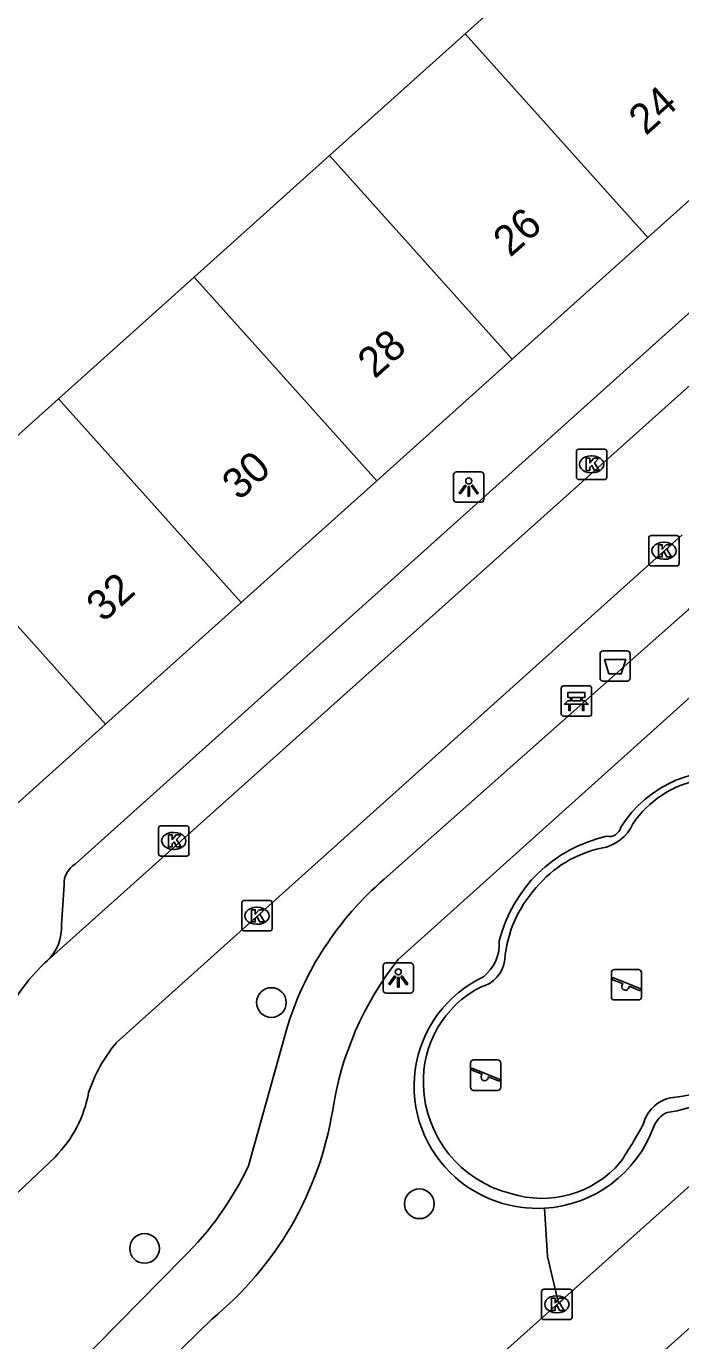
# Model space of a CAD drawing. Extents: x 162172 to 163187, y 382874 to 383684.
# Drawn here: x 162860.48 to 162882.03, y 383428.41 to 383471.71 of the extents above; entities that cross this region are included whole.
import ezdxf

# ---------------------------------------------------------------- set-up
doc = ezdxf.new("R2010")
doc.units = 0
for name, color, linetype in [('IMGEO_Afvalbak', 7, 'Continuous'), ('IMGEO_Bank', 7, 'Continuous'), ('IMGEO_Berm_groen', 7, 'Continuous'), ('IMGEO_Boom', 7, 'Continuous'), ('IMGEO_Haag', 7, 'Continuous'), ('IMGEO_Kolk', 7, 'Continuous'), ('IMGEO_Lichtpunt', 7, 'Continuous'), ('IMGEO_Pand', 7, 'Continuous'), ('IMGEO_Pand_nummerreeks', 7, 'Continuous'), ('IMGEO_Rijbaan_lokaal_open', 7, 'Continuous'), ('IMGEO_Speelvoorziening', 7, 'Continuous'), ('IMGEO_Terreindeel_open', 7, 'Continuous'), ('IMGEO_Voetpad_open', 7, 'Continuous')]:
    doc.layers.add(name, color=color, linetype=linetype)

msp = doc.modelspace()

# ---------------------------------------------------------------- linework, layer by layer
at = {"layer": 'IMGEO_Afvalbak'}
for p, q in [((162879.479, 383451.136), (162880.269, 383451.136)), ((162880.269, 383451.136), (162879.479, 383451.136)), ((162879.379, 383450.236), (162879.379, 383451.036)), ((162879.379, 383451.036), (162879.379, 383450.236)), ((162880.369, 383451.036), (162880.369, 383450.236)), ((162880.369, 383450.236), (162880.369, 383451.036)), ((162880.269, 383450.136), (162879.479, 383450.136)), ((162879.479, 383450.136), (162880.269, 383450.136))]:
    msp.add_line(p, q, dxfattribs=at)
msp.add_lwpolyline([(162879.522, 383450.85), (162880.226, 383450.85), (162880.077, 383450.38), (162879.671, 383450.38), (162879.522, 383450.85)], dxfattribs=at)
for centre, start, end in [((162879.479, 383451.036), 90, 180), ((162879.479, 383451.036), 90, 180), ((162880.269, 383451.036), 0, 90), ((162880.269, 383451.036), 360, 90), ((162879.479, 383450.236), 180, 270), ((162879.479, 383450.236), 180, 270), ((162880.269, 383450.236), 270, 0), ((162880.269, 383450.236), 270, 0)]:
    msp.add_arc(centre, 0.1, start, end, dxfattribs=at)
at = {"layer": 'IMGEO_Bank'}
for p, q in [((162878.1, 383449.06), (162878.1, 383449.901)), ((162878.1, 383449.901), (162878.1, 383449.06)), ((162878.175, 383449.985), (162879.016, 383449.985)), ((162879.016, 383449.985), (162878.175, 383449.985)), ((162879.1, 383449.91), (162879.1, 383449.069)), ((162879.1, 383449.069), (162879.1, 383449.91)), ((162878.797, 383449.383), (162878.404, 383449.383)), ((162878.409, 383449.491), (162878.409, 383449.597)), ((162878.453, 383449.597), (162878.453, 383449.491)), ((162878.741, 383449.603), (162878.459, 383449.603)), ((162878.459, 383449.485), (162878.741, 383449.485)), ((162878.747, 383449.491), (162878.747, 383449.597)), ((162878.791, 383449.597), (162878.791, 383449.491)), ((162879.025, 383448.985), (162878.184, 383448.985)), ((162878.184, 383448.985), (162879.025, 383448.985))]:
    msp.add_line(p, q, dxfattribs=at)
for points in [[(162878.403, 383449.603), (162878.317, 383449.603), (162878.317, 383449.764), (162878.88, 383449.764), (162878.88, 383449.603), (162878.797, 383449.603)], [(162878.347, 383449.383), (162878.205, 383449.383), (162878.317, 383449.485), (162878.403, 383449.485)], [(162878.397, 383449.376), (162878.397, 383449.169), (162878.354, 383449.169), (162878.354, 383449.376)], [(162878.797, 383449.485), (162878.88, 383449.485), (162878.992, 383449.383), (162878.853, 383449.383)], [(162878.847, 383449.376), (162878.847, 383449.169), (162878.803, 383449.169), (162878.803, 383449.376)]]:
    msp.add_lwpolyline(points, dxfattribs=at)
for centre, radius, start, end in [((162878.178, 383449.907), 0.0779, 92.4484, 184.2845), ((162878.178, 383449.907), 0.0779, 92.4484, 184.2845), ((162879.022, 383449.907), 0.0779, 2.4484, 94.2845), ((162879.022, 383449.907), 0.0779, 2.4484, 94.2845), ((162878.347, 383449.376), 0.00671, 2.8957, 87.1043), ((162878.404, 383449.376), 0.00671, 92.8957, 177.1043), ((162878.402, 383449.596), 0.00671, 2.8957, 87.1043), ((162878.402, 383449.492), 0.00671, 272.8957, 357.1043), ((162878.459, 383449.596), 0.00671, 92.8957, 177.1043), ((162878.459, 383449.492), 0.00671, 182.8957, 267.1043), ((162878.741, 383449.596), 0.00671, 2.8957, 87.1043), ((162878.741, 383449.492), 0.00671, 272.8957, 357.1043), ((162878.798, 383449.596), 0.00671, 92.8957, 177.1043), ((162878.798, 383449.492), 0.00671, 182.8957, 267.1043), ((162878.796, 383449.376), 0.00671, 2.8957, 87.1043), ((162878.853, 383449.376), 0.00671, 92.8957, 177.1043), ((162878.178, 383449.063), 0.0779, 182.4484, 274.2845), ((162878.178, 383449.063), 0.0779, 182.4484, 274.2845), ((162879.022, 383449.063), 0.0779, 272.4484, 4.2845), ((162879.022, 383449.063), 0.0779, 272.4484, 4.2845)]:
    msp.add_arc(centre, radius, start, end, dxfattribs=at)
at = {"layer": 'IMGEO_Berm_groen'}
for centre, radius, start, end in [((162883.45, 383443.191), 4.004, 9.0634, 147.8309), ((162880.6, 383440.457), 4.678, 102.4127, 166.06), ((162879.676, 383445.413), 0.395, 258.0117, 346.899), ((162874.663, 383441.491), 1.399, 308.7042, 3.8292), ((162877.24, 383436.792), 3.988, 115.2604, 228.8582), ((162877.313, 383436.845), 4.076, 228.5736, 273.2824)]:
    msp.add_arc(centre, radius, start, end, dxfattribs=at)
at = {"layer": 'IMGEO_Boom'}
for centre in [(162868.552, 383439.551), (162873.426, 383432.921), (162864.375, 383431.45)]:
    msp.add_circle(centre, 0.489, dxfattribs=at)
at = {"layer": 'IMGEO_Haag'}
msp.add_lwpolyline([(162877.546, 383432.776), (162877.648, 383431.184), (162878.014, 383429.65)], dxfattribs=at)
for centre, radius, start, end in [((162881.087, 383440.039), 4.137, 276.9729, 349.396), ((162881.998, 383435.107), 0.922, 116.3265, 157.1983), ((162877.312, 383436.846), 4.077, 273.2851, 340.1793)]:
    msp.add_arc(centre, radius, start, end, dxfattribs=at)
at = {"layer": 'IMGEO_Kolk'}
for p, q in [((162878.6, 383456.853), (162878.6, 383457.705)), ((162878.675, 383457.779), (162879.527, 383457.779)), ((162879.088, 383457.559), (162879.113, 383457.559)), ((162879.601, 383457.705), (162879.601, 383456.853)), ((162879.527, 383456.779), (162878.675, 383456.779)), ((162879.111, 383456.999), (162879.086, 383456.999)), ((162880.982, 383454.005), (162880.982, 383454.857)), ((162881.057, 383454.931), (162881.909, 383454.931)), ((162881.47, 383454.711), (162881.495, 383454.711)), ((162881.983, 383454.857), (162881.983, 383454.005)), ((162881.493, 383454.151), (162881.468, 383454.151)), ((162881.909, 383453.931), (162881.057, 383453.931)), ((162864.838, 383444.45), (162864.838, 383445.302)), ((162864.913, 383445.376), (162865.765, 383445.376)), ((162865.326, 383445.156), (162865.351, 383445.156)), ((162865.839, 383445.302), (162865.839, 383444.45)), ((162865.349, 383444.596), (162865.324, 383444.596)), ((162865.765, 383444.376), (162864.913, 383444.376)), ((162867.576, 383441.982), (162867.576, 383442.834)), ((162867.651, 383442.908), (162868.503, 383442.908)), ((162868.577, 383442.834), (162868.577, 383441.982)), ((162868.064, 383442.688), (162868.089, 383442.688)), ((162868.087, 383442.128), (162868.062, 383442.128)), ((162868.503, 383441.908), (162867.651, 383441.908)), ((162877.454, 383429.183), (162877.454, 383430.035)), ((162877.529, 383430.109), (162878.381, 383430.109)), ((162877.942, 383429.889), (162877.967, 383429.889)), ((162878.455, 383430.035), (162878.455, 383429.183)), ((162878.381, 383429.109), (162877.529, 383429.109)), ((162877.965, 383429.329), (162877.94, 383429.329))]:
    msp.add_line(p, q, dxfattribs=at)
for points in [[(162878.6, 383456.853), (162878.6, 383457.705)], [(162878.675, 383457.779), (162879.527, 383457.779)], [(162879.601, 383457.705), (162879.601, 383456.853)], [(162878.921, 383457.479), (162879.044, 383457.479), (162879.044, 383457.328), (162879.174, 383457.479), (162879.338, 383457.479), (162879.192, 383457.328), (162879.345, 383457.079), (162879.193, 383457.079), (162879.108, 383457.243), (162879.044, 383457.176), (162879.044, 383457.079), (162878.921, 383457.079), (162878.921, 383457.479)], [(162879.527, 383456.779), (162878.675, 383456.779)], [(162880.982, 383454.005), (162880.982, 383454.857)], [(162881.057, 383454.931), (162881.909, 383454.931)], [(162881.303, 383454.631), (162881.426, 383454.631), (162881.426, 383454.48), (162881.556, 383454.631), (162881.72, 383454.631), (162881.574, 383454.48), (162881.727, 383454.231), (162881.575, 383454.231), (162881.49, 383454.395), (162881.426, 383454.328), (162881.426, 383454.231), (162881.303, 383454.231), (162881.303, 383454.631)], [(162881.983, 383454.857), (162881.983, 383454.005)], [(162881.909, 383453.931), (162881.057, 383453.931)], [(162864.838, 383444.45), (162864.838, 383445.302)], [(162864.913, 383445.376), (162865.765, 383445.376)], [(162865.159, 383445.076), (162865.282, 383445.076), (162865.282, 383444.925), (162865.412, 383445.076), (162865.576, 383445.076), (162865.43, 383444.925), (162865.583, 383444.676), (162865.431, 383444.676), (162865.346, 383444.84), (162865.282, 383444.773), (162865.282, 383444.676), (162865.159, 383444.676), (162865.159, 383445.076)], [(162865.839, 383445.302), (162865.839, 383444.45)], [(162865.765, 383444.376), (162864.913, 383444.376)], [(162867.576, 383441.982), (162867.576, 383442.834)], [(162867.651, 383442.908), (162868.503, 383442.908)], [(162868.577, 383442.834), (162868.577, 383441.982)], [(162867.897, 383442.608), (162868.02, 383442.608), (162868.02, 383442.457), (162868.15, 383442.608), (162868.314, 383442.608), (162868.168, 383442.457), (162868.321, 383442.208), (162868.169, 383442.208), (162868.084, 383442.372), (162868.02, 383442.305), (162868.02, 383442.208), (162867.897, 383442.208), (162867.897, 383442.608)], [(162868.503, 383441.908), (162867.651, 383441.908)], [(162877.454, 383429.183), (162877.454, 383430.035)], [(162877.529, 383430.109), (162878.381, 383430.109)], [(162878.455, 383430.035), (162878.455, 383429.183)], [(162877.775, 383429.809), (162877.898, 383429.809), (162877.898, 383429.658), (162878.028, 383429.809), (162878.192, 383429.809), (162878.046, 383429.658), (162878.199, 383429.409), (162878.047, 383429.409), (162877.962, 383429.573), (162877.898, 383429.506), (162877.898, 383429.409), (162877.775, 383429.409), (162877.775, 383429.809)], [(162878.381, 383429.109), (162877.529, 383429.109)]]:
    msp.add_lwpolyline(points, dxfattribs=at)
for centre, start, end in [((162878.677, 383457.703), 91.552, 178.448), ((162878.677, 383457.703), 91.552, 178.448), ((162879.525, 383457.703), 1.552, 88.448), ((162879.525, 383457.703), 1.552, 88.448), ((162878.677, 383456.855), 181.552, 268.448), ((162878.677, 383456.855), 181.552, 268.448), ((162879.525, 383456.855), 271.552, 358.448), ((162879.525, 383456.855), 271.552, 358.448), ((162881.059, 383454.855), 91.552, 178.448), ((162881.059, 383454.855), 91.552, 178.448), ((162881.907, 383454.855), 1.552, 88.448), ((162881.907, 383454.855), 1.552, 88.448), ((162881.059, 383454.007), 181.552, 268.448), ((162881.059, 383454.007), 181.552, 268.448), ((162881.907, 383454.007), 271.552, 358.448), ((162881.907, 383454.007), 271.552, 358.448), ((162864.915, 383445.3), 91.552, 178.448), ((162864.915, 383445.3), 91.552, 178.448), ((162865.763, 383445.3), 1.552, 88.448), ((162865.763, 383445.3), 1.552, 88.448), ((162864.915, 383444.452), 181.552, 268.448), ((162864.915, 383444.452), 181.552, 268.448), ((162865.763, 383444.452), 271.552, 358.448), ((162865.763, 383444.452), 271.552, 358.448), ((162867.653, 383442.832), 91.552, 178.448), ((162867.653, 383442.832), 91.552, 178.448), ((162868.501, 383442.832), 1.552, 88.448), ((162868.501, 383442.832), 1.552, 88.448), ((162867.653, 383441.984), 181.552, 268.448), ((162867.653, 383441.984), 181.552, 268.448), ((162868.501, 383441.984), 271.552, 358.448), ((162868.501, 383441.984), 271.552, 358.448), ((162877.531, 383430.033), 91.552, 178.448), ((162877.531, 383430.033), 91.552, 178.448), ((162878.379, 383430.033), 1.552, 88.448), ((162878.379, 383430.033), 1.552, 88.448), ((162877.531, 383429.185), 181.552, 268.448), ((162877.531, 383429.185), 181.552, 268.448), ((162878.379, 383429.185), 271.552, 358.448), ((162878.379, 383429.185), 271.552, 358.448)]:
    msp.add_arc(centre, 0.0765, start, end, dxfattribs=at)
for centre, major_axis, ratio, start_param, end_param in [((162879.087, 383457.279), (-0.387, 0.002), 0.722429, 4.712389, 7.853982), ((162879.112, 383457.279), (-0.39, 0.002), 0.717154, 1.570796, 4.712389), ((162881.469, 383454.431), (-0.387, 0.002), 0.722429, 4.712389, 7.853982), ((162881.494, 383454.431), (-0.39, 0.002), 0.717154, 1.570796, 4.712389), ((162865.325, 383444.876), (-0.387, 0.002), 0.722429, 4.712389, 7.853982), ((162865.35, 383444.876), (-0.39, 0.002), 0.717154, 1.570796, 4.712389), ((162868.063, 383442.408), (-0.387, 0.002), 0.722429, 4.712389, 7.853982), ((162868.088, 383442.408), (-0.39, 0.002), 0.717154, 1.570796, 4.712389), ((162877.941, 383429.609), (-0.387, 0.002), 0.722429, 4.712389, 7.853982), ((162877.966, 383429.609), (-0.39, 0.002), 0.717154, 1.570796, 4.712389)]:
    msp.add_ellipse(centre, major_axis=major_axis, ratio=ratio, start_param=start_param, end_param=end_param, dxfattribs=at)
at = {"layer": 'IMGEO_Lichtpunt'}
for p, q in [((162874.554, 383456.934), (162874.554, 383456.127)), ((162874.554, 383456.934), (162874.554, 383456.127)), ((162875.456, 383457.029), (162874.648, 383457.029)), ((162875.456, 383457.029), (162874.648, 383457.029)), ((162875.55, 383456.127), (162875.55, 383456.934)), ((162875.55, 383456.127), (162875.55, 383456.934)), ((162874.648, 383456.033), (162875.456, 383456.033)), ((162874.648, 383456.033), (162875.456, 383456.033)), ((162872.234, 383440.763), (162872.234, 383439.956)), ((162872.234, 383440.763), (162872.234, 383439.956)), ((162873.136, 383440.858), (162872.328, 383440.858)), ((162873.136, 383440.858), (162872.328, 383440.858)), ((162873.23, 383439.956), (162873.23, 383440.763)), ((162873.23, 383439.956), (162873.23, 383440.763)), ((162872.328, 383439.862), (162873.136, 383439.862)), ((162872.328, 383439.862), (162873.136, 383439.862))]:
    msp.add_line(p, q, dxfattribs=at)
for points in [[(162874.928, 383456.598), (162874.967, 383456.57), (162874.779, 383456.308), (162874.741, 383456.335), (162874.928, 383456.598)], [(162875.03, 383456.55), (162875.077, 383456.55), (162875.077, 383456.228), (162875.03, 383456.228), (162875.03, 383456.55)], [(162875.14, 383456.57), (162875.178, 383456.597), (162875.365, 383456.335), (162875.326, 383456.307), (162875.14, 383456.57)], [(162872.608, 383440.427), (162872.647, 383440.399), (162872.459, 383440.137), (162872.421, 383440.164), (162872.608, 383440.427)], [(162872.71, 383440.379), (162872.757, 383440.379), (162872.757, 383440.057), (162872.71, 383440.057), (162872.71, 383440.379)], [(162872.82, 383440.399), (162872.858, 383440.426), (162873.045, 383440.164), (162873.006, 383440.136), (162872.82, 383440.399)]]:
    msp.add_lwpolyline(points, dxfattribs=at)
for centre in [(162875.053, 383456.732), (162872.733, 383440.561)]:
    msp.add_circle(centre, 0.0994, dxfattribs=at)
for centre, start, end in [((162874.648, 383456.934), 90, 180), ((162874.648, 383456.934), 90, 180), ((162875.456, 383456.934), 0, 90), ((162875.456, 383456.934), 0, 90), ((162874.648, 383456.127), 180, 270), ((162874.648, 383456.127), 180, 270), ((162875.456, 383456.127), 270, 0), ((162875.456, 383456.127), 270, 360), ((162872.328, 383440.763), 90, 180), ((162872.328, 383440.763), 90, 180), ((162873.136, 383440.763), 0, 90), ((162873.136, 383440.763), 0, 90), ((162872.328, 383439.956), 180, 270), ((162872.328, 383439.956), 180, 270), ((162873.136, 383439.956), 270, 0), ((162873.136, 383439.956), 270, 360)]:
    msp.add_arc(centre, 0.0946, start, end, dxfattribs=at)
at = {"layer": 'IMGEO_Pand'}
for points in [[(162874.934, 383471.458), (162879.399, 383475.466)], [(162870.469, 383467.45), (162874.934, 383471.458)], [(162874.934, 383471.458), (162880.951, 383464.755)], [(162880.951, 383464.755), (162885.417, 383468.762)], [(162866.005, 383463.441), (162870.469, 383467.45)], [(162876.486, 383460.747), (162870.469, 383467.45)], [(162876.486, 383460.747), (162880.951, 383464.755)], [(162861.54, 383459.433), (162866.005, 383463.441)], [(162866.005, 383463.441), (162872.021, 383456.74)], [(162872.021, 383456.74), (162876.486, 383460.747)], [(162857.076, 383455.424), (162861.54, 383459.433)], [(162867.555, 383452.732), (162861.54, 383459.433)], [(162872.021, 383456.74), (162867.555, 383452.732)], [(162863.09, 383448.725), (162857.076, 383455.424)], [(162863.09, 383448.725), (162867.555, 383452.732)], [(162858.625, 383444.717), (162863.09, 383448.725)]]:
    msp.add_lwpolyline(points, dxfattribs=at)
at = {"layer": 'IMGEO_Rijbaan_lokaal_open'}
for points in [[(162861.182, 383440.936), (162913.384, 383487.689)], [(162876.516, 383423.635), (162925.505, 383467.463)], [(162882.086, 383454.952), (162863.448, 383438.229)], [(162861.096, 383440.858), (162861.182, 383440.936)], [(162878.014, 383429.65), (162887.106, 383437.789), (162887.215, 383437.886)], [(162861.426, 383434.462), (162856.84, 383430.135)], [(162874.367, 383426.385), (162878.014, 383429.65)]]:
    msp.add_lwpolyline(points, dxfattribs=at)
for centre, radius, start, end in [((162864.815, 383436.819), 5.49, 132.6414, 164.6787), ((162867.379, 383434.958), 5.114, 140.2414, 161.4185), ((162858.596, 383437.285), 3.997, 315.071, 349.9598)]:
    msp.add_arc(centre, radius, start, end, dxfattribs=at)
at = {"layer": 'IMGEO_Speelvoorziening'}
for p, q in [((162879.752, 383439.737), (162879.752, 383440.537)), ((162879.752, 383440.537), (162879.752, 383439.737)), ((162880.135, 383440.165), (162879.796, 383440.302)), ((162879.821, 383440.362), (162880.697, 383440.009)), ((162879.852, 383440.637), (162880.642, 383440.637)), ((162880.642, 383440.637), (162879.852, 383440.637)), ((162880.742, 383440.537), (162880.742, 383439.737)), ((162880.742, 383439.737), (162880.742, 383440.537)), ((162880.673, 383439.949), (162880.333, 383440.086)), ((162880.642, 383439.637), (162879.852, 383439.637)), ((162879.852, 383439.637), (162880.642, 383439.637)), ((162875.215, 383437.658), (162876.005, 383437.658)), ((162876.005, 383437.658), (162875.215, 383437.658)), ((162875.115, 383436.758), (162875.115, 383437.558)), ((162875.115, 383437.558), (162875.115, 383436.758)), ((162875.498, 383437.186), (162875.159, 383437.323)), ((162875.184, 383437.383), (162876.06, 383437.03)), ((162876.105, 383437.558), (162876.105, 383436.758)), ((162876.105, 383436.758), (162876.105, 383437.558)), ((162876.036, 383436.97), (162875.696, 383437.107)), ((162876.005, 383436.658), (162875.215, 383436.658)), ((162875.215, 383436.658), (162876.005, 383436.658))]:
    msp.add_line(p, q, dxfattribs=at)
for centre, radius, start, end in [((162879.852, 383440.537), 0.1, 90, 180), ((162879.852, 383440.537), 0.1, 90, 180), ((162879.809, 383440.332), 0.0327, 68.078, 248.078), ((162880.642, 383440.537), 0.1, 0, 90), ((162880.642, 383440.537), 0.1, 360, 90), ((162880.214, 383440.075), 0.12, 130.9928, 5.1632), ((162880.685, 383439.979), 0.0327, 248.078, 68.078), ((162879.852, 383439.737), 0.1, 180, 270), ((162879.852, 383439.737), 0.1, 180, 270), ((162880.642, 383439.737), 0.1, 270, 0), ((162880.642, 383439.737), 0.1, 270, 0), ((162875.215, 383437.558), 0.1, 90, 180), ((162875.215, 383437.558), 0.1, 90, 180), ((162876.005, 383437.558), 0.1, 0, 90), ((162876.005, 383437.558), 0.1, 360, 90), ((162875.172, 383437.353), 0.0327, 68.078, 248.078), ((162875.577, 383437.096), 0.12, 130.9928, 5.1632), ((162875.215, 383436.758), 0.1, 180, 270), ((162875.215, 383436.758), 0.1, 180, 270), ((162876.005, 383436.758), 0.1, 270, 0), ((162876.005, 383436.758), 0.1, 270, 0), ((162876.048, 383437), 0.0327, 248.078, 68.078)]:
    msp.add_arc(centre, radius, start, end, dxfattribs=at)
at = {"layer": 'IMGEO_Terreindeel_open'}
for centre, radius, start, end in [((162883.309, 383443.509), 3.442, 100.6035, 145.9259), ((162879.195, 383445.997), 1.381, 279.3823, 336.138), ((162880.205, 383440.913), 3.803, 101.9144, 140.4206), ((162880.269, 383440.619), 4.044, 137.7875, 175.1059), ((162875.191, 383441.086), 1.056, 283.5668, 353.3473), ((162877.045, 383436.965), 3.487, 117.4257, 182.3939), ((162881.644, 383439.466), 3.039, 274.2737, 343.4144), ((162877.346, 383436.937), 3.786, 181.7861, 256.0698), ((162881.963, 383435.243), 1.2, 111.0312, 164.7272), ((162881.941, 383435.288), 1.15, 93.5439, 110.8307), ((162870.357, 383440.961), 11.762, 325.4277, 332.658), ((162877.472, 383436.473), 3.374, 252.0912, 319.6276)]:
    msp.add_arc(centre, radius, start, end, dxfattribs=at)
at = {"layer": 'IMGEO_Voetpad_open'}
for points in [[(162862.086, 383444.109), (162909.797, 383486.956)], [(162882.44, 383452.633), (162882.275, 383452.487), (162872.272, 383443.617)], [(162885.253, 383452.223), (162872.726, 383440.968)], [(162861.635, 383442.109), (162861.723, 383443.432)], [(162869.046, 383438.656), (162867.799, 383434.174)], [(162865.643, 383431.15), (162859.183, 383424.602)], [(162866.588, 383429.125), (162860.482, 383423.161)]]:
    msp.add_lwpolyline(points, dxfattribs=at)
for centre, radius, start, end in [((162862.487, 383443.458), 0.764, 121.6217, 181.9788), ((162879.151, 383435.614), 10.553, 130.683, 163.2473), ((162860.143, 383442.011), 1.495, 314.0136, 3.7544), ((162881.068, 383434.396), 10.619, 141.768, 171.2813), ((162859.505, 383437.818), 11.214, 309.173, 350.699), ((162858.455, 383438.555), 10.32, 314.1463, 334.8787)]:
    msp.add_arc(centre, radius, start, end, dxfattribs=at)

# ---------------------------------------------------------------- texts
at = {"layer": 'IMGEO_Pand_nummerreeks'}
for s, p in [('24', (162880.885, 383468.083)), ('26', (162876.42, 383464.075)), ('28', (162871.957, 383460.07)), ('30', (162867.492, 383456.062)), ('32', (162863.022, 383452.051))]:
    msp.add_text(s, height=1, rotation=41.9067, dxfattribs=at).set_placement(p)

doc.saveas('drawing.dxf')
